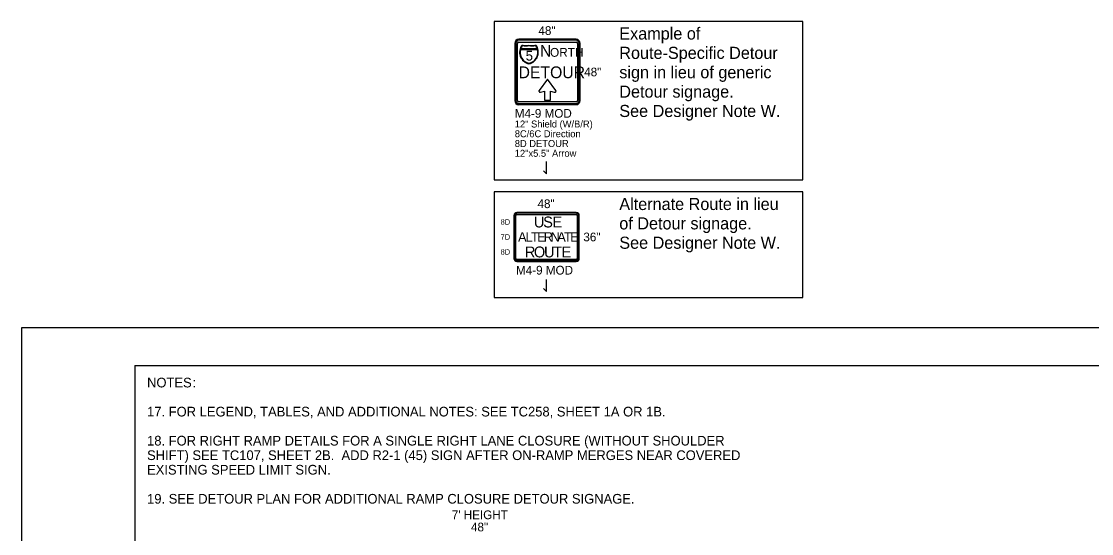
# Model space of a CAD drawing. Extents: x 99999 to 100116, y 99995 to 100013.
# Drawn here: x 100059.06 to 100067.9, y 100008.99 to 100013.22 of the extents above; entities that cross this region are included whole.
import ezdxf

# ---------------------------------------------------------------- set-up
doc = ezdxf.new("R2010")
doc.units = 0
for name, color, linetype in [('SH_GI_GeneralNotesBodyText', 7, 'Continuous'), ('SH_GI_PlotLimits', 7, 'Continuous'), ('SH_GI_SheetBorder', 7, 'Continuous'), ('TR_SN_ConstructionSigns', 7, 'Continuous'), ('TR_WZ_WorkZoneDetails', 7, 'Continuous')]:
    doc.layers.add(name, color=color, linetype=linetype)

msp = doc.modelspace()

# ---------------------------------------------------------------- linework, layer by layer
at = {"layer": 'SH_GI_PlotLimits'}
msp.add_lwpolyline([(100059.0625, 99999.6875), (100076.0625, 99999.6875), (100076.0625, 100010.6875), (100059.0625, 100010.6875)], close=True, dxfattribs=at)
at = {"layer": 'SH_GI_SheetBorder'}
for q in [(100060, 100000), (100075.75, 100010.375)]:
    msp.add_line((100060, 100010.375), q, dxfattribs=at)
at = {"layer": 'TR_SN_ConstructionSigns'}
for p, q in [((100063.1354, 100013.0373), (100063.1354, 100012.5648)), ((100063.1438, 100013.0373), (100063.1438, 100012.5648)), ((100063.1579, 100012.5648), (100063.1579, 100013.0373)), ((100063.6416, 100013.0711), (100063.1691, 100013.0711)), ((100063.6416, 100013.0626), (100063.1691, 100013.0626)), ((100063.1691, 100013.0486), (100063.6416, 100013.0486)), ((100063.6529, 100013.0373), (100063.6529, 100012.5648)), ((100063.6669, 100012.5648), (100063.6669, 100013.0373)), ((100063.6754, 100012.5648), (100063.6754, 100013.0373)), ((100063.3228, 100012.9875), (100063.1823, 100012.9875)), ((100063.1823, 100012.9875), (100063.3228, 100012.9875)), ((100063.1834, 100012.9912), (100063.3217, 100012.9912)), ((100063.3217, 100012.9912), (100063.1834, 100012.9912)), ((100063.6416, 100012.5536), (100063.1691, 100012.5536)), ((100063.1691, 100012.5395), (100063.6416, 100012.5395)), ((100063.1691, 100012.5311), (100063.6416, 100012.5311)), ((100063.6424, 100011.6405), (100063.153, 100011.6405)), ((100063.6424, 100011.6335), (100063.153, 100011.6335)), ((100063.153, 100011.6236), (100063.6424, 100011.6236)), ((100063.1277, 100011.6152), (100063.1277, 100011.2608)), ((100063.1347, 100011.6152), (100063.1347, 100011.2608)), ((100063.1446, 100011.2608), (100063.1446, 100011.6152)), ((100063.6508, 100011.6152), (100063.6508, 100011.2608)), ((100063.6607, 100011.2608), (100063.6607, 100011.6152)), ((100063.6677, 100011.2608), (100063.6677, 100011.6152)), ((100063.6424, 100011.2524), (100063.153, 100011.2524)), ((100063.153, 100011.2425), (100063.6424, 100011.2425)), ((100063.153, 100011.2355), (100063.6424, 100011.2355))]:
    msp.add_line(p, q, dxfattribs=at)
msp.add_lwpolyline([(100063.3367, 100012.6494), (100063.3356, 100012.6478), (100063.335, 100012.6461), (100063.3347, 100012.6441), (100063.3348, 100012.6424), (100063.335, 100012.6412), (100063.3356, 100012.6398), (100063.3373, 100012.6375), (100063.3386, 100012.6364), (100063.34, 100012.6355), (100063.3417, 100012.6348), (100063.3432, 100012.6345), (100063.3447, 100012.6343), (100063.3465, 100012.6343), (100063.3478, 100012.6346), (100063.3795, 100012.6424), (100063.3795, 100012.5671), (100063.4307, 100012.5671), (100063.4307, 100012.6429), (100063.4617, 100012.6337), (100063.4647, 100012.6331), (100063.4681, 100012.6334), (100063.4703, 100012.6342), (100063.4733, 100012.6362), (100063.4752, 100012.6389), (100063.476, 100012.6414), (100063.4761, 100012.6436), (100063.4754, 100012.6463), (100063.4746, 100012.6477), (100063.4051, 100012.7405), (100063.3367, 100012.6494)], dxfattribs=at)
for centre, radius, start, end in [((100063.1691, 100013.0373), 0.0337, 90, 180), ((100063.1691, 100013.0373), 0.0253, 90, 180), ((100063.1691, 100013.0373), 0.0113, 90, 180), ((100063.6416, 100013.0373), 0.0338, 360, 90), ((100063.6416, 100013.0373), 0.0253, 360, 90), ((100063.6416, 100013.0373), 0.0113, 360, 90), ((100063.2725, 100012.9642), 0.0973, 142.16169, 258.18105), ((100063.2715, 100012.9633), 0.0925, 164.85517, 258.18105), ((100063.2715, 100012.9633), 0.0925, 164.85517, 258.18105), ((100063.2715, 100012.9633), 0.0925, 142.16169, 162.48397), ((100063.2715, 100012.9633), 0.0925, 142.16169, 162.48397), ((100063.2245, 100013.1212), 0.1014, 253.48525, 286.04538), ((100063.2259, 100013.1124), 0.0964, 253.48525, 286.04538), ((100063.2259, 100013.1124), 0.0964, 253.48525, 286.04538), ((100063.2806, 100013.1212), 0.1014, 253.95462, 286.51475), ((100063.2792, 100013.1124), 0.0964, 253.95462, 286.51475), ((100063.2792, 100013.1124), 0.0964, 253.95462, 286.51475), ((100063.2325, 100012.9642), 0.0974, 281.90384, 37.84925), ((100063.2335, 100012.9633), 0.0925, 281.90384, 15.1558), ((100063.2335, 100012.9633), 0.0925, 281.90384, 15.1558), ((100063.2335, 100012.9633), 0.0925, 17.52691, 37.84925), ((100063.2335, 100012.9633), 0.0925, 17.52691, 37.84925), ((100063.1691, 100012.5648), 0.0338, 180, 270), ((100063.1691, 100012.5648), 0.0253, 180, 270), ((100063.1691, 100012.5648), 0.0113, 180, 270), ((100063.6416, 100012.5648), 0.0337, 270, 360), ((100063.6416, 100012.5648), 0.0253, 270, 0), ((100063.6416, 100012.5648), 0.0113, 270, 0), ((100063.153, 100011.6152), 0.0253, 90, 180), ((100063.153, 100011.6152), 0.0183, 90, 180), ((100063.153, 100011.6152), 0.00844, 90, 180), ((100063.6424, 100011.6152), 0.0253, 360, 90), ((100063.6424, 100011.6152), 0.0183, 360, 90), ((100063.6424, 100011.6152), 0.00844, 360, 90), ((100063.153, 100011.2608), 0.0253, 180, 270), ((100063.153, 100011.2608), 0.0183, 180, 270), ((100063.153, 100011.2608), 0.00844, 180, 270), ((100063.6424, 100011.2608), 0.0253, 270, 360), ((100063.6424, 100011.2608), 0.0183, 270, 0), ((100063.6424, 100011.2608), 0.00844, 270, 0)]:
    msp.add_arc(centre, radius, start, end, dxfattribs=at)
at = {"layer": 'TR_WZ_WorkZoneDetails'}
for p, q in [((100063.3963, 100011.9605), (100063.3963, 100012.0605)), ((100063.3713, 100011.9855), (100063.3963, 100011.9605)), ((100063.3963, 100010.9875), (100063.3963, 100011.0875)), ((100063.3713, 100011.0125), (100063.3963, 100010.9875))]:
    msp.add_line(p, q, dxfattribs=at)
for points in [[(100062.9666, 100011.9105), (100065.5143, 100011.9105), (100065.5143, 100013.2191), (100062.9666, 100013.2191)], [(100062.9666, 100010.9375), (100065.5143, 100010.9375), (100065.5143, 100011.8105), (100062.9666, 100011.8105)]]:
    msp.add_lwpolyline(points, close=True, dxfattribs=at)

# ---------------------------------------------------------------- texts
at = {"layer": 'SH_GI_GeneralNotesBodyText'}
for s, p in [('NOTES', (100060.1, 100010.195)), (':', (100060.4743, 100010.195)), ('17. FOR LEGEND, TABLES, AND ADDITIONAL NOTES: SEE TC258, SHEET 1A OR 1B.', (100060.1, 100009.955)), ('18. FOR RIGHT RAMP DETAILS FOR A SINGLE RIGHT LANE CLOSURE (WITHOUT SHOULDER ', (100060.1, 100009.715)), ('SHIFT) SEE TC107, SHEET 2B.  ADD R2-1 (45) SIGN AFTER ON-RAMP MERGES NEAR COVERED ', (100060.1, 100009.595)), ('EXISTING SPEED LIMIT SIGN.', (100060.1, 100009.475)), ('19. SEE DETOUR PLAN FOR ADDITIONAL RAMP CLOSURE DETOUR SIGNAGE.', (100060.1, 100009.235))]:
    msp.add_text(s, height=0.08, rotation=360, dxfattribs=at).set_placement(p)
at = {"layer": 'TR_SN_ConstructionSigns'}
for s, height, p in [('48"', 0.072, (100063.3306, 100013.1071)), ('5', 0.081, (100063.2253, 100012.8951)), ('N', 0.0972, (100063.3432, 100012.9267)), ('ORTH', 0.0729, (100063.4264, 100012.9267)), ('DETOUR', 0.0972, (100063.1668, 100012.7497)), ('48"', 0.072, (100063.7086, 100012.7651)), ('M4-9 MOD', 0.072, (100063.1354, 100012.4231)), ('12" Shield (W/B/R)', 0.0576, (100063.1354, 100012.3424)), ('8C/6C Direction', 0.0576, (100063.1354, 100012.2618)), ('8D DETOUR', 0.0576, (100063.1354, 100012.1811)), ('12"x5.5" Arrow', 0.0576, (100063.1354, 100012.1005)), ('48"', 0.072, (100063.323, 100011.6765)), ('36"', 0.072, (100063.7015, 100011.402)), ('M4-9 MOD', 0.072, (100063.1457, 100011.1275)), ("7' HEIGHT", 0.072, (100062.6156, 100009.1065)), ('48"', 0.072, (100062.774, 100009.0057))]:
    msp.add_text(s, height=height, rotation=360, dxfattribs=at).set_placement(p)
for s, height, p in [('8D', 0.045, (100063.018, 100011.5392)), ('U', 0.09, (100063.2933, 100011.5167)), ('S', 0.09, (100063.3698, 100011.5167)), ('E', 0.09, (100063.4463, 100011.5167)), ('7D', 0.045, (100063.018, 100011.4155)), ('A', 0.0787, (100063.1626, 100011.3986)), ('L', 0.0787, (100063.2241, 100011.3986)), ('T', 0.0787, (100063.269, 100011.3986)), ('E', 0.0787, (100063.3201, 100011.3986)), ('R', 0.0787, (100063.3737, 100011.3986)), ('N', 0.0787, (100063.4312, 100011.3986)), ('A', 0.0787, (100063.4863, 100011.3986)), ('T', 0.0787, (100063.5414, 100011.3986)), ('E', 0.0787, (100063.5926, 100011.3986)), ('R', 0.09, (100063.2186, 100011.2692)), ('O', 0.09, (100063.2933, 100011.2692)), ('U', 0.09, (100063.377, 100011.2692)), ('T', 0.09, (100063.4517, 100011.2692)), ('E', 0.09, (100063.521, 100011.2692)), ('8D', 0.045, (100063.018, 100011.2917))]:
    msp.add_text(s, height=height, dxfattribs=at).set_placement(p)
at = {"layer": 'TR_WZ_WorkZoneDetails'}
for s, p in [('Example of ', (100063.9983, 100013.0691)), ('Route-Specific Detour ', (100063.9983, 100012.9091)), ('sign in lieu of generic ', (100063.9983, 100012.7491)), ('Detour signage.', (100063.9983, 100012.5891)), ('See Designer Note W.', (100063.9983, 100012.4291)), ('Alternate Route in lieu ', (100063.9983, 100011.6605)), ('of Detour signage.', (100063.9983, 100011.5005)), ('See Designer Note W.', (100063.9983, 100011.3405))]:
    msp.add_text(s, height=0.1, dxfattribs=at).set_placement(p)

doc.saveas('drawing.dxf')
